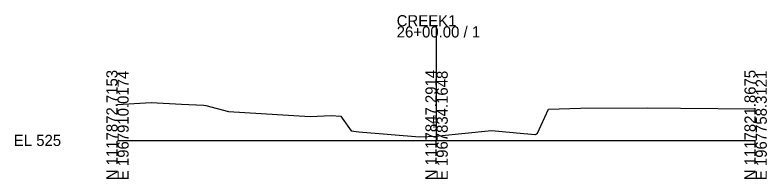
# Model space of a CAD drawing. Extents: x -26 to 163, y -10 to 10052.
# Drawn here: x -25.7 to 162.8, y 5490.3 to 5531.5 of the extents above; entities that cross this region are included whole.
import ezdxf

# ---------------------------------------------------------------- set-up
doc = ezdxf.new("R2010")
doc.units = 0
for name, color, linetype in [('RD_GPK_XS_Cell', 7, 'Continuous'), ('RD_XS_ExGround', 7, 'Continuous'), ('RD_XS_TX_Elev_EX', 7, 'Continuous')]:
    doc.layers.add(name, color=color, linetype=linetype)

msp = doc.modelspace()

# ---------------------------------------------------------------- linework, layer by layer
at = {"layer": 'RD_GPK_XS_Cell'}
for p, q in [((80, 5500), (80, 5528.64)), ((0, 5500), (80, 5500)), ((80, 5500), (160, 5500))]:
    msp.add_line(p, q, dxfattribs=at)
at = {"layer": 'RD_XS_ExGround'}
for p, q in [((0, 5508.98), (8.48, 5509.55)), ((8.48, 5509.55), (16.03, 5509.06)), ((16.03, 5509.06), (21.61, 5508.83)), ((21.61, 5508.83), (22.16, 5508.76)), ((22.16, 5508.76), (27.85, 5507.27)), ((27.85, 5507.27), (48.33, 5506.01)), ((105.28, 5501.84), (108.1, 5507.81)), ((108.1, 5507.81), (116.07, 5508.12)), ((116.07, 5508.12), (133.01, 5508.15)), ((133.01, 5508.15), (141.2, 5508.12)), ((141.2, 5508.12), (160, 5507.93)), ((48.33, 5506.01), (53.54, 5506.23)), ((53.54, 5506.23), (55.98, 5506.06)), ((55.98, 5506.06), (56.34, 5505.57)), ((56.34, 5505.57), (58.58, 5502.41)), ((58.58, 5502.41), (60.47, 5502.11)), ((60.47, 5502.11), (75.74, 5500.85)), ((80.54, 5501.11), (93.76, 5502.47)), ((93.76, 5502.47), (101.87, 5501.72)), ((101.87, 5501.72), (104.84, 5501.46)), ((104.84, 5501.46), (105.28, 5501.84)), ((75.74, 5500.85), (80, 5501.08)), ((80, 5501.08), (80.54, 5501.11))]:
    msp.add_line(p, q, dxfattribs=at)

# ---------------------------------------------------------------- texts
at = {"layer": 'RD_GPK_XS_Cell'}
for s, p in [('CREEK1', (70, 5528.64)), ('26+00.00 / 1', (70, 5525.84)), ('EL 525', (-26, 5498.6))]:
    msp.add_text(s, height=2.8, dxfattribs=at).set_placement(p)
for s, p in [('N 1117872.7153', (0, 5490)), ('E 1967910.0174', (2.8, 5490)), ('N 1117847.2914', (80, 5490)), ('E 1967834.1648', (82.8, 5490)), ('N 1117821.8675', (160, 5490)), ('E 1967758.3121', (162.8, 5490))]:
    msp.add_text(s, height=2.8, rotation=90, dxfattribs=at).set_placement(p)
at = {"layer": 'RD_XS_TX_Elev_EX'}
msp.add_text('526.08', height=0.8, rotation=90, dxfattribs=at).set_placement((79.9, 5503.08))

doc.saveas('drawing.dxf')
